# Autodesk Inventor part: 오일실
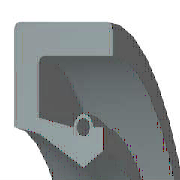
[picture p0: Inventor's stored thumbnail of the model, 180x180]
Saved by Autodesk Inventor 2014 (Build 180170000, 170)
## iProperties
Created: 2009-02
Part Number: 오일실
Material: Rubber
Description: 오일-실
Document SubType Name: Modeling
Standard: KS B 2804
Designer: KYOUNG IL JANG
Standards Organization: KS
Language: ko-KR
Size Designation: S - 18 30 8
Categories: <MemberInstance><Categories><Category DisplayName="샤프트 부품" InternalName="7f7aeb1f-a693-4053-b835-cee3144e0d98" Mnemonic="SHFT"><Category DisplayName="실링" Intern
Density: 0.93 g/cm^3
Appearance: Rubber - Black - Version 1.1
Company: 한국ATC센터
IsCustomPart: 1
Author: KYOUNG IL JANG
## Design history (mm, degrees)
revolve "본체" stored, may be unused: angle "d17" = 90 deg
revolve "스프링1" stored, may be unused: angle "d18" = 90 deg
body "Solid1"
sketch "스케치1"
  geometry: L1 (0, 15)-(8, 15); L2 (8, 15)-(8, 13.75); L3 (8, 13.75)-(1.75, 13.75); L4 (0, 15)-(0, 11.1); L5 (0, 11.1)-(1.75, 10.75); L6 (1.75, 10.75)-(4.9, 9); L7 (4.9, 9)-(0, 9); L8 (6.3, 9.875)-(6.3, 11.1); L9 (0, 0)-(9.586, 0) reference; L10 (4.9, 9)-(6.3, 9.875); L11 (0, 18)-(0, -3) reference; L12 (-1.917, 0)-(11.503, 0) reference; L13 (4.2, 11.1)-(1.75, 11.59); L14 (1.75, 11.59)-(1.75, 13.75); L15 (6.3, 11.1)-(5.6, 11.1); C1 r 0.455 at (4.9, 11.1); A1 r 0.7 centre (4.9, 11.1) between (5.6, 11.1) and (4.2, 11.1)
  constraints: 26 end point, 5 horizontal alignment, 4 perpendicular, 2 centre point, 2 collinear, 2 horizontal, 2 parallel, 2 point on circle, 2 point on line, 2 vertical alignment, 1 coincident
  dimensions: "d0" = 30 diameter of L1 L9 (= SD2); "d1" = 19.75 diameter of L8.start L9 (= ABDM); "d2" = 1.25 distance of L1.end L2.end (computed from SD); "d3" = 0.91 diameter of C1 (= SPDI); "d4" = 1.4 diameter of A1 (= SPDA); "d5" = 18 diameter of L6.end L9 (= NND); "d6" = 21.5 diameter of L5.end L9 (= TKDM); "d7" = 22.2 diameter of L4.end L9 (= HLDM); "d8" = 4.9 distance from line of C1.centre L4 (= SPDST); "d9" = 6.3 distance between parallel lines of L8 L4 (= SDI); "d10" = 8 distance between parallel lines of L2 L4 (= SWDT); "d12" = 1.75 distance between parallel lines of L14 L4 (= SD)
fillet "모깎기1" dims "d11" = 0.3 (= RR)
other parameters: "SD2" = 30 [user parameter; used in 1 equation term], "SWDT" = 8 [user parameter; used in 1 equation term], "RR" = 0.3 [user parameter; used in 1 equation term], "SD" = 1.75 [user parameter; used in 2 equation terms], "NND" = 18 [user parameter; used in 1 equation term], "SPDA" = 1.4 [user parameter; used in 1 equation term], "SPDI" = 0.91 [user parameter; used in 1 equation term], "TKDM" = 21.5 [user parameter; used in 1 equation term], "HLDM" = 22.2 [user parameter; used in 1 equation term], "ABDM" = 19.75 [user parameter; used in 1 equation term], "SDI" = 6.3 [user parameter; used in 1 equation term], "SPDST" = 4.9 [user parameter; used in 1 equation term], "d13" = 0, "d14" = 0, "d15" = 0, "LAB" = 0.35 [user parameter]
